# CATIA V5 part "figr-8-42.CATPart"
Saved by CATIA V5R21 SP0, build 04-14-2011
Part number: Part1
Bounding box of the stored display mesh (mm): x -75 to 75, y -75 to 75, z 0 to 20
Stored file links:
  D:\CATIA V5R21 E-RESOURCES\CATIA-V5R21\catia-v5r21-prt\c08-catia-v5r20-prt\c08-catia-v5r21-figr-8-42.CATPart
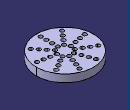
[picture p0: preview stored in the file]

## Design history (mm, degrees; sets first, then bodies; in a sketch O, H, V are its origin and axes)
Body1 (main body)
  Sketch1 on xy-plane, origin (0, 0, 0), H (1, 0, 0), V (0, 1, 0)
    circle A1 centre (0, 0) radius 75
    point P1 (75, 0)
    radius A1 = 75
    coincidence: A1 P1, P1 H
  Pad1: profile Sketch1, direction (0, 0, 1), length 20
  Sketch2 on face of Pad1, origin (0, 0, 20), H (1, 0, 0), V (0, 1, 0)
    circle A1 centre (0, -18.7232) radius 5.1678
    point P1 (0, -18.7232)
    coincidence: P1 V
  Pocket1: profile Sketch2, direction (0, 0, -1), through (limit type 3)
  CircPattern1: of Pocket1, instances 9, angular step 40 {= 360.0*1 deg/CircPattern1.AngularNumber}, circles 4, radial step 15, axis from face of Pad1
